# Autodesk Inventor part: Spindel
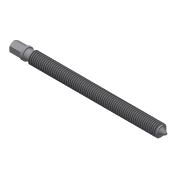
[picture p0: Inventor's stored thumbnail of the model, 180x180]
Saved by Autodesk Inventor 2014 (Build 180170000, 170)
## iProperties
Company: VDW-Nachwuchsstiftung
Created: 2014-03
Part Number: Spindel
Material: Generisch
Document SubType Name: Modeling
Designer: e_dammj
Density: 1 g/cm^3
Appearance: Vorgabe
Author: e_dammj
Title: Spindel
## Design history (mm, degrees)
sketch "Skizze1"
  geometry: L1 (0, 0)-(0, 0.75); L2 (-4, 4)-(-5, 4); L3 (-5, 4)-(-5, 5); L4 (-5, 5)-(-113, 5); L5 (-113, 5)-(-113, 4); L6 (-113, 4)-(-118, 4); L7 (-118, 4)-(-118, 5); L8 (-118, 5)-(-129.365, 5); L9 (-130, 0)-(0, 0); L10 (-129.365, 5)-(-130, 3.9); L11 (-130, 3.9)-(-130, 0); L12 (0, 0.75)-(-4, 3.059); L13 (-4, 3.059)-(-4, 4)
  constraints: 26 end point, 7 parallel, 3 perpendicular, 1 collinear, 1 vertical
  dimensions: "d0" = 1.5 diameter of L1.end L9; "d1" = 8 diameter of L2 L9; "d2" = 10 diameter of L4 L9; "d3" = 4 distance from line of L2.start L1; "d4" = 5 distance from line of L1 L2.end; "d6" = 10 diameter of L8 L9; "d7" = 130 distance between parallel lines of L1 L11; "d8" = 7.8 diameter of L10.end L9; "d10" = 30 deg angle of L11 L10; "d11" = 8 diameter of L6 L9; "d12" = 5 distance between parallel lines of L5 L7; "d13" = 17 distance between parallel lines of L11 L5; "d14" = 30 deg angle of L12 L9 (derived)
revolve "Umdrehung1" sketch "Skizze1" stored, may be unused: angle "d15" = 90 deg
sketch "Skizze2"
  geometry: L1 (2.309, 4)-(4.619, 0); L2 (4.619, 0)-(2.309, -4); L3 (2.309, -4)-(-2.309, -4); L4 (-2.309, -4)-(-4.619, 0); L5 (-4.619, 0)-(-2.309, 4); L6 (-2.309, 4)-(2.309, 4); C1 r 3.9 at (0, 0) reference; C2 r 5 at (0, 0) reference; 3 further points
  constraints: 12 end point, 2 midpoint, 1 coincident, 1 vertical alignment, 13 other
  dimensions: "d17" = 8 distance between parallel lines of L2 L5
extrude "Extrusion1" cut sketch "Skizze2" distance "d18" = 10; taper "d19" = 0 deg
feature "Gewinde1" dims "d20" = 10, "d21" = 0
node "Volumenkörper1"
